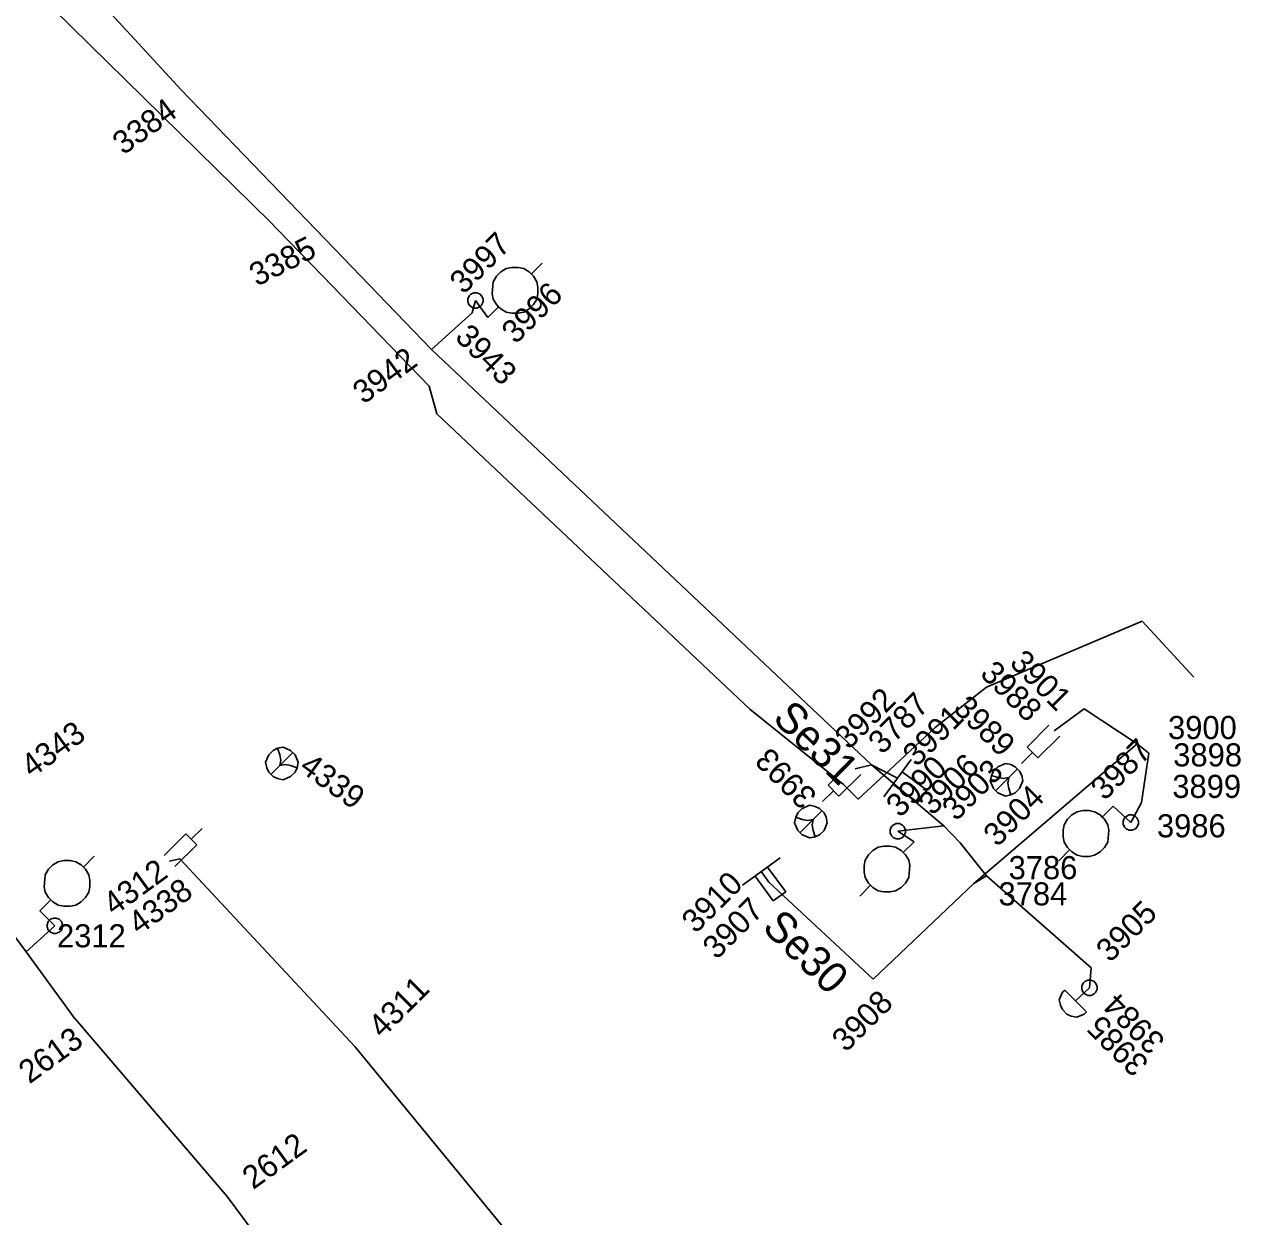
# Model space of a CAD drawing. Extents: x -535557 to -534097, y -1142175 to -1136716.
# Drawn here: x -534981.31 to -534941.83, y -1138903.19 to -1138864.49 of the extents above; entities that cross this region are included whole.
import ezdxf

# ---------------------------------------------------------------- set-up
doc = ezdxf.new("R2010")
doc.units = 0
for name, color, linetype in [('Default', 7, 'Continuous'), ('GIS_vektor_sdelovaci_kabely_CD', 7, 'Continuous'), ('SS_SZDC', 7, 'Continuous')]:
    doc.layers.add(name, color=color, linetype=linetype)

# ---------------------------------------------------------------- blocks, each defined once
blk = doc.blocks.new('POINT_DISPLAY')
at = {"layer": 'Default'}
blk.add_line((0, 0), (0, 0), dxfattribs=at)

msp = doc.modelspace()

# ---------------------------------------------------------------- linework, layer by layer
at = {"layer": 'GIS_vektor_sdelovaci_kabely_CD'}
msp.add_lwpolyline([(-534980.378, -1138863.98), (-534973.325, -1138870.913), (-534973.094, -1138871.151), (-534971.638, -1138872.653), (-534968.166, -1138876.234), (-534967.918, -1138877.131), (-534957.767, -1138886.721), (-534954.728, -1138889.162), (-534954.252, -1138889.638), (-534953.383, -1138888.842), (-534951.746, -1138887.317), (-534950.076, -1138886.002), (-534945.025, -1138883.863), (-534943.35, -1138885.685)], dxfattribs=at)
at = {"layer": 'SS_SZDC'}
for p, q in [((-534986.09, -1138855.87), (-534976.22, -1138866.62)), ((-534976.22, -1138866.62), (-534972.13, -1138870.86)), ((-534972.13, -1138870.86), (-534968.09, -1138875.04)), ((-534965.845, -1138872.525), (-534965.668, -1138872.419)), ((-534965.668, -1138872.419), (-534965.492, -1138872.383)), ((-534965.492, -1138872.383), (-534965.28, -1138872.383)), ((-534965.28, -1138872.383), (-534965.103, -1138872.419)), ((-534965.103, -1138872.419), (-534964.926, -1138872.525)), ((-534964.855, -1138872.595), (-534964.502, -1138872.242)), ((-534966.128, -1138873.232), (-534966.093, -1138872.843)), ((-534966.093, -1138872.843), (-534965.987, -1138872.666)), ((-534965.987, -1138872.666), (-534965.845, -1138872.525)), ((-534964.926, -1138872.525), (-534964.785, -1138872.666)), ((-534964.785, -1138872.666), (-534964.679, -1138872.843)), ((-534964.679, -1138872.843), (-534964.643, -1138873.02)), ((-534966.87, -1138873.3), (-534966.82, -1138873.25)), ((-534966.82, -1138873.25), (-534966.72, -1138873.2)), ((-534966.72, -1138873.2), (-534966.62, -1138873.2)), ((-534966.62, -1138873.2), (-534966.52, -1138873.25)), ((-534966.52, -1138873.25), (-534966.47, -1138873.3)), ((-534966.093, -1138873.408), (-534966.128, -1138873.232)), ((-534964.643, -1138873.232), (-534964.679, -1138873.408)), ((-534964.643, -1138873.02), (-534964.643, -1138873.232)), ((-534966.92, -1138873.4), (-534966.87, -1138873.3)), ((-534966.92, -1138873.5), (-534966.92, -1138873.4)), ((-534966.87, -1138873.6), (-534966.92, -1138873.5)), ((-534966.82, -1138873.65), (-534966.87, -1138873.6)), ((-534966.72, -1138873.7), (-534966.82, -1138873.65)), ((-534966.77, -1138873.85), (-534966.67, -1138873.45)), ((-534966.67, -1138873.45), (-534966.27, -1138874.01)), ((-534966.52, -1138873.65), (-534966.62, -1138873.7)), ((-534966.47, -1138873.6), (-534966.52, -1138873.65)), ((-534966.47, -1138873.3), (-534966.42, -1138873.4)), ((-534966.42, -1138873.5), (-534966.47, -1138873.6)), ((-534966.42, -1138873.4), (-534966.42, -1138873.5)), ((-534966.27, -1138874.01), (-534965.916, -1138873.656)), ((-534965.987, -1138873.585), (-534966.093, -1138873.408)), ((-534965.916, -1138873.656), (-534965.987, -1138873.585)), ((-534965.845, -1138873.727), (-534965.916, -1138873.656)), ((-534964.785, -1138873.585), (-534964.926, -1138873.727)), ((-534964.679, -1138873.408), (-534964.785, -1138873.585)), ((-534968.09, -1138875.04), (-534966.77, -1138873.85)), ((-534966.62, -1138873.7), (-534966.72, -1138873.7)), ((-534965.668, -1138873.833), (-534965.845, -1138873.727)), ((-534965.492, -1138873.868), (-534965.668, -1138873.833)), ((-534965.28, -1138873.868), (-534965.492, -1138873.868)), ((-534965.103, -1138873.833), (-534965.28, -1138873.868)), ((-534964.926, -1138873.727), (-534965.103, -1138873.833)), ((-534968.09, -1138875.04), (-534953.819, -1138888.53)), ((-534946.909, -1138886.709), (-534947.88, -1138887.42)), ((-534945.189, -1138887.84), (-534946.909, -1138886.709)), ((-534948.763, -1138887.95), (-534948.056, -1138887.243)), ((-534950.489, -1138892.379), (-534945.189, -1138887.84)), ((-534947.703, -1138887.596), (-534948.41, -1138888.303)), ((-534945.189, -1138887.84), (-534944.81, -1138888.149)), ((-534973.48, -1138888.444), (-534973.374, -1138888.197)), ((-534973.374, -1138888.197), (-534973.232, -1138888.055)), ((-534972.596, -1138888.126), (-534973.303, -1138888.833)), ((-534973.232, -1138888.055), (-534973.091, -1138887.985)), ((-534973.091, -1138887.985), (-534972.914, -1138887.949)), ((-534973.02, -1138888.197), (-534973.091, -1138887.985)), ((-534972.985, -1138888.373), (-534973.02, -1138888.197)), ((-534972.914, -1138887.949), (-534972.667, -1138888.055)), ((-534972.667, -1138888.055), (-534972.525, -1138888.197)), ((-534972.525, -1138888.197), (-534972.419, -1138888.444)), ((-534948.587, -1138888.127), (-534948.94, -1138888.48)), ((-534948.41, -1138888.303), (-534948.763, -1138887.95)), ((-534944.81, -1138888.149), (-534945.05, -1138889.75)), ((-534973.444, -1138888.621), (-534973.48, -1138888.444)), ((-534973.374, -1138888.762), (-534973.444, -1138888.621)), ((-534973.02, -1138888.55), (-534972.985, -1138888.373)), ((-534973.02, -1138888.55), (-534972.843, -1138888.515)), ((-534972.843, -1138888.515), (-534972.667, -1138888.55)), ((-534972.667, -1138888.55), (-534972.455, -1138888.621)), ((-534972.455, -1138888.621), (-534972.525, -1138888.762)), ((-534972.419, -1138888.444), (-534972.455, -1138888.621)), ((-534955.223, -1138889.19), (-534954.516, -1138888.483)), ((-534953.819, -1138888.53), (-534954.34, -1138888.659)), ((-534953.819, -1138888.53), (-534951.47, -1138890.51)), ((-534953.819, -1138888.53), (-534952.97, -1138888.959)), ((-534952.529, -1138888.353), (-534953.41, -1138889.566)), ((-534949.854, -1138888.727), (-534949.712, -1138888.585)), ((-534949.783, -1138889.363), (-534949.076, -1138888.656)), ((-534949.712, -1138888.585), (-534949.465, -1138888.479)), ((-534949.465, -1138888.479), (-534949.288, -1138888.515)), ((-534949.288, -1138888.515), (-534949.147, -1138888.585)), ((-534949.147, -1138888.585), (-534949.005, -1138888.727)), ((-534973.232, -1138888.904), (-534973.374, -1138888.762)), ((-534973.091, -1138888.974), (-534973.232, -1138888.904)), ((-534972.914, -1138889.01), (-534973.091, -1138888.974)), ((-534972.667, -1138888.904), (-534972.914, -1138889.01)), ((-534972.525, -1138888.762), (-534972.667, -1138888.904)), ((-534954.163, -1138888.836), (-534954.87, -1138889.543)), ((-534952.823, -1138888.757), (-534952.014, -1138889.345)), ((-534949.96, -1138889.045), (-534949.924, -1138888.868)), ((-534949.854, -1138889.292), (-534949.96, -1138889.045)), ((-534949.924, -1138888.868), (-534949.854, -1138888.727)), ((-534949.712, -1138888.939), (-534949.924, -1138888.868)), ((-534949.536, -1138888.974), (-534949.712, -1138888.939)), ((-534949.359, -1138888.939), (-534949.536, -1138888.974)), ((-534949.359, -1138888.939), (-534949.394, -1138889.116)), ((-534949.005, -1138888.727), (-534948.935, -1138888.868)), ((-534948.899, -1138889.045), (-534949.005, -1138889.292)), ((-534948.935, -1138888.868), (-534948.899, -1138889.045)), ((-534955.047, -1138889.367), (-534955.4, -1138889.72)), ((-534954.87, -1138889.543), (-534955.223, -1138889.19)), ((-534952.307, -1138889.75), (-534953.116, -1138889.162)), ((-534952.014, -1138889.345), (-534952.307, -1138889.75)), ((-534949.712, -1138889.434), (-534949.854, -1138889.292)), ((-534949.465, -1138889.54), (-534949.712, -1138889.434)), ((-534949.394, -1138889.116), (-534949.359, -1138889.292)), ((-534949.359, -1138889.292), (-534949.288, -1138889.504)), ((-534949.147, -1138889.434), (-534949.288, -1138889.504)), ((-534949.005, -1138889.292), (-534949.147, -1138889.434)), ((-534956.062, -1138889.945), (-534955.815, -1138889.839)), ((-534955.815, -1138889.839), (-534955.638, -1138889.875)), ((-534949.288, -1138889.504), (-534949.465, -1138889.54)), ((-534945.05, -1138889.75), (-534945.399, -1138890.399)), ((-534956.31, -1138890.405), (-534956.274, -1138890.228)), ((-534956.274, -1138890.228), (-534956.204, -1138890.087)), ((-534956.062, -1138890.299), (-534956.274, -1138890.228)), ((-534956.204, -1138890.087), (-534956.062, -1138889.945)), ((-534956.133, -1138890.723), (-534955.426, -1138890.016)), ((-534955.638, -1138889.875), (-534955.497, -1138889.945)), ((-534955.497, -1138889.945), (-534955.355, -1138890.087)), ((-534955.355, -1138890.087), (-534955.285, -1138890.228)), ((-534955.285, -1138890.228), (-534955.249, -1138890.405)), ((-534947.454, -1138890.294), (-534947.313, -1138890.152)), ((-534947.313, -1138890.152), (-534947.136, -1138890.046)), ((-534947.136, -1138890.046), (-534946.959, -1138890.011)), ((-534946.959, -1138890.011), (-534946.747, -1138890.011)), ((-534946.747, -1138890.011), (-534946.571, -1138890.046)), ((-534946.571, -1138890.046), (-534946.394, -1138890.152)), ((-534946.394, -1138890.152), (-534946.323, -1138890.223)), ((-534945.97, -1138889.87), (-534946.323, -1138890.223)), ((-534946.323, -1138890.223), (-534946.252, -1138890.294)), ((-534945.399, -1138890.399), (-534945.97, -1138889.87)), ((-534945.649, -1138890.349), (-534945.599, -1138890.249)), ((-534945.599, -1138890.249), (-534945.549, -1138890.199)), ((-534945.549, -1138890.199), (-534945.449, -1138890.149)), ((-534945.449, -1138890.149), (-534945.349, -1138890.149)), ((-534945.349, -1138890.149), (-534945.249, -1138890.199)), ((-534945.249, -1138890.199), (-534945.199, -1138890.249)), ((-534945.199, -1138890.249), (-534945.149, -1138890.349)), ((-534975.892, -1138890.942), (-534975.539, -1138890.589)), ((-534956.204, -1138890.652), (-534956.31, -1138890.405)), ((-534956.062, -1138890.794), (-534956.204, -1138890.652)), ((-534955.886, -1138890.334), (-534956.062, -1138890.299)), ((-534955.709, -1138890.299), (-534955.886, -1138890.334)), ((-534955.709, -1138890.299), (-534955.744, -1138890.476)), ((-534955.744, -1138890.476), (-534955.709, -1138890.652)), ((-534955.709, -1138890.652), (-534955.638, -1138890.864)), ((-534955.355, -1138890.652), (-534955.497, -1138890.794)), ((-534955.249, -1138890.405), (-534955.355, -1138890.652)), ((-534953.21, -1138890.63), (-534953.16, -1138890.53)), ((-534953.21, -1138890.73), (-534953.21, -1138890.63)), ((-534953.16, -1138890.53), (-534953.11, -1138890.48)), ((-534953.11, -1138890.48), (-534953.01, -1138890.43)), ((-534953.01, -1138890.43), (-534952.91, -1138890.43)), ((-534951.47, -1138890.51), (-534952.96, -1138890.68)), ((-534952.91, -1138890.43), (-534952.81, -1138890.48)), ((-534952.81, -1138890.48), (-534952.76, -1138890.53)), ((-534952.76, -1138890.53), (-534952.71, -1138890.63)), ((-534952.71, -1138890.63), (-534952.71, -1138890.73)), ((-534951.47, -1138890.51), (-534950.939, -1138891.059)), ((-534947.596, -1138890.647), (-534947.56, -1138890.471)), ((-534947.596, -1138890.859), (-534947.596, -1138890.647)), ((-534947.56, -1138890.471), (-534947.454, -1138890.294)), ((-534946.252, -1138890.294), (-534946.146, -1138890.471)), ((-534946.146, -1138890.471), (-534946.111, -1138890.647)), ((-534946.111, -1138890.647), (-534946.146, -1138891.036)), ((-534945.649, -1138890.449), (-534945.649, -1138890.349)), ((-534945.599, -1138890.549), (-534945.649, -1138890.449)), ((-534945.549, -1138890.599), (-534945.599, -1138890.549)), ((-534945.449, -1138890.649), (-534945.549, -1138890.599)), ((-534945.349, -1138890.649), (-534945.449, -1138890.649)), ((-534945.249, -1138890.599), (-534945.349, -1138890.649)), ((-534945.199, -1138890.549), (-534945.249, -1138890.599)), ((-534945.149, -1138890.449), (-534945.199, -1138890.549)), ((-534945.149, -1138890.349), (-534945.149, -1138890.449)), ((-534976.776, -1138891.473), (-534976.069, -1138890.766)), ((-534976.069, -1138890.766), (-534975.716, -1138891.119)), ((-534955.815, -1138890.9), (-534956.062, -1138890.794)), ((-534955.638, -1138890.864), (-534955.815, -1138890.9)), ((-534955.497, -1138890.794), (-534955.638, -1138890.864)), ((-534953.16, -1138890.83), (-534953.21, -1138890.73)), ((-534953.11, -1138890.88), (-534953.16, -1138890.83)), ((-534953.01, -1138890.93), (-534953.11, -1138890.88)), ((-534952.91, -1138890.93), (-534953.01, -1138890.93)), ((-534952.96, -1138890.68), (-534952.43, -1138891.02)), ((-534952.81, -1138890.88), (-534952.91, -1138890.93)), ((-534952.76, -1138890.83), (-534952.81, -1138890.88)), ((-534952.43, -1138891.02), (-534952.783, -1138891.373)), ((-534952.71, -1138890.73), (-534952.76, -1138890.83)), ((-534947.56, -1138891.036), (-534947.596, -1138890.859)), ((-534947.454, -1138891.213), (-534947.56, -1138891.036)), ((-534946.146, -1138891.036), (-534946.252, -1138891.213)), ((-534983.869, -1138891.069), (-534981.25, -1138894.6)), ((-534975.716, -1138891.119), (-534976.423, -1138891.826)), ((-534954.02, -1138891.621), (-534953.914, -1138891.444)), ((-534953.914, -1138891.444), (-534953.773, -1138891.302)), ((-534953.773, -1138891.302), (-534953.596, -1138891.196)), ((-534953.596, -1138891.196), (-534953.419, -1138891.161)), ((-534953.419, -1138891.161), (-534953.207, -1138891.161)), ((-534953.207, -1138891.161), (-534953.031, -1138891.196)), ((-534953.031, -1138891.196), (-534952.854, -1138891.302)), ((-534952.854, -1138891.302), (-534952.783, -1138891.373)), ((-534952.783, -1138891.373), (-534952.712, -1138891.444)), ((-534952.712, -1138891.444), (-534952.606, -1138891.621)), ((-534950.939, -1138891.059), (-534950.079, -1138892.129)), ((-534947.384, -1138891.284), (-534947.737, -1138891.637)), ((-534947.313, -1138891.354), (-534947.454, -1138891.213)), ((-534947.136, -1138891.46), (-534947.313, -1138891.354)), ((-534946.394, -1138891.354), (-534946.571, -1138891.46)), ((-534946.252, -1138891.213), (-534946.394, -1138891.354)), ((-534980.527, -1138891.916), (-534980.385, -1138891.775)), ((-534980.385, -1138891.775), (-534980.208, -1138891.669)), ((-534980.208, -1138891.669), (-534980.032, -1138891.633)), ((-534980.032, -1138891.633), (-534979.82, -1138891.633)), ((-534979.82, -1138891.633), (-534979.643, -1138891.669)), ((-534979.643, -1138891.669), (-534979.466, -1138891.775)), ((-534979.466, -1138891.775), (-534979.325, -1138891.916)), ((-534979.395, -1138891.845), (-534979.042, -1138891.492)), ((-534976.26, -1138891.579), (-534976.6, -1138891.649)), ((-534970.579, -1138897.67), (-534976.26, -1138891.579)), ((-534956.783, -1138891.549), (-534957.996, -1138892.43)), ((-534954.056, -1138891.797), (-534954.02, -1138891.621)), ((-534954.056, -1138892.009), (-534954.056, -1138891.797)), ((-534952.606, -1138891.621), (-534952.571, -1138891.797)), ((-534952.571, -1138891.797), (-534952.606, -1138892.186)), ((-534946.959, -1138891.496), (-534947.136, -1138891.46)), ((-534946.747, -1138891.496), (-534946.959, -1138891.496)), ((-534946.571, -1138891.46), (-534946.747, -1138891.496)), ((-534980.668, -1138892.482), (-534980.633, -1138892.093)), ((-534980.633, -1138892.093), (-534980.527, -1138891.916)), ((-534979.325, -1138891.916), (-534979.219, -1138892.093)), ((-534979.219, -1138892.093), (-534979.183, -1138892.27)), ((-534957.004, -1138892.945), (-534957.592, -1138892.136)), ((-534957.149, -1138892.329), (-534957.39, -1138891.989)), ((-534957.187, -1138891.843), (-534956.599, -1138892.652)), ((-534954.02, -1138892.186), (-534954.056, -1138892.009)), ((-534953.914, -1138892.363), (-534954.02, -1138892.186)), ((-534952.606, -1138892.186), (-534952.712, -1138892.363)), ((-534950.079, -1138892.129), (-534950.489, -1138892.379)), ((-534950.079, -1138892.129), (-534946.689, -1138895.12)), ((-534980.633, -1138892.658), (-534980.668, -1138892.482)), ((-534979.183, -1138892.482), (-534979.219, -1138892.658)), ((-534979.183, -1138892.27), (-534979.183, -1138892.482)), ((-534953.76, -1138895.479), (-534957.149, -1138892.329)), ((-534953.844, -1138892.434), (-534954.197, -1138892.787)), ((-534953.773, -1138892.504), (-534953.914, -1138892.363)), ((-534953.596, -1138892.61), (-534953.773, -1138892.504)), ((-534950.489, -1138892.379), (-534953.76, -1138895.479)), ((-534953.419, -1138892.646), (-534953.596, -1138892.61)), ((-534953.031, -1138892.61), (-534953.207, -1138892.646)), ((-534952.854, -1138892.504), (-534953.031, -1138892.61)), ((-534952.712, -1138892.363), (-534952.854, -1138892.504)), ((-534980.81, -1138893.26), (-534980.456, -1138892.906)), ((-534980.527, -1138892.835), (-534980.633, -1138892.658)), ((-534980.456, -1138892.906), (-534980.527, -1138892.835)), ((-534980.385, -1138892.977), (-534980.456, -1138892.906)), ((-534980.208, -1138893.083), (-534980.385, -1138892.977)), ((-534979.466, -1138892.977), (-534979.643, -1138893.083)), ((-534979.325, -1138892.835), (-534979.466, -1138892.977)), ((-534979.219, -1138892.658), (-534979.325, -1138892.835)), ((-534956.599, -1138892.652), (-534957.004, -1138892.945)), ((-534953.207, -1138892.646), (-534953.419, -1138892.646)), ((-534980.319, -1138893.75), (-534980.81, -1138893.26)), ((-534980.032, -1138893.118), (-534980.208, -1138893.083)), ((-534979.82, -1138893.118), (-534980.032, -1138893.118)), ((-534979.643, -1138893.083), (-534979.82, -1138893.118)), ((-534981.25, -1138894.6), (-534980.319, -1138893.75)), ((-534980.567, -1138893.714), (-534980.532, -1138893.608)), ((-534980.567, -1138893.785), (-534980.567, -1138893.714)), ((-534980.532, -1138893.891), (-534980.567, -1138893.785)), ((-534980.532, -1138893.608), (-534980.461, -1138893.537)), ((-534980.461, -1138893.537), (-534980.355, -1138893.502)), ((-534980.355, -1138893.502), (-534980.284, -1138893.502)), ((-534980.284, -1138893.502), (-534980.178, -1138893.537)), ((-534980.178, -1138893.537), (-534980.107, -1138893.608)), ((-534980.107, -1138893.608), (-534980.072, -1138893.714)), ((-534980.072, -1138893.785), (-534980.107, -1138893.891)), ((-534980.072, -1138893.714), (-534980.072, -1138893.785)), ((-534980.461, -1138893.962), (-534980.532, -1138893.891)), ((-534980.355, -1138893.997), (-534980.461, -1138893.962)), ((-534980.284, -1138893.997), (-534980.355, -1138893.997)), ((-534980.178, -1138893.962), (-534980.284, -1138893.997)), ((-534980.107, -1138893.891), (-534980.178, -1138893.962)), ((-534979.71, -1138896.7), (-534981.25, -1138894.6)), ((-534946.689, -1138895.12), (-534946.739, -1138895.76)), ((-534946.739, -1138895.76), (-534947.189, -1138896.19)), ((-534946.989, -1138895.71), (-534946.939, -1138895.61)), ((-534946.989, -1138895.81), (-534946.989, -1138895.71)), ((-534946.939, -1138895.61), (-534946.889, -1138895.56)), ((-534946.889, -1138895.56), (-534946.789, -1138895.51)), ((-534946.789, -1138895.51), (-534946.689, -1138895.51)), ((-534946.689, -1138895.51), (-534946.589, -1138895.56)), ((-534946.589, -1138895.56), (-534946.539, -1138895.61)), ((-534946.539, -1138895.61), (-534946.489, -1138895.71)), ((-534946.489, -1138895.71), (-534946.489, -1138895.81)), ((-534947.614, -1138895.907), (-534947.72, -1138896.154)), ((-534947.72, -1138896.154), (-534947.684, -1138896.331)), ((-534947.543, -1138895.836), (-534947.614, -1138895.907)), ((-534946.836, -1138896.543), (-534947.543, -1138895.836)), ((-534946.939, -1138895.91), (-534946.989, -1138895.81)), ((-534946.889, -1138895.96), (-534946.939, -1138895.91)), ((-534946.789, -1138896.01), (-534946.889, -1138895.96)), ((-534946.689, -1138896.01), (-534946.789, -1138896.01)), ((-534946.589, -1138895.96), (-534946.689, -1138896.01)), ((-534946.539, -1138895.91), (-534946.589, -1138895.96)), ((-534946.489, -1138895.81), (-534946.539, -1138895.91)), ((-534947.684, -1138896.331), (-534947.614, -1138896.472)), ((-534947.614, -1138896.472), (-534947.472, -1138896.614)), ((-534946.907, -1138896.614), (-534946.836, -1138896.543)), ((-534979.71, -1138896.7), (-534974.729, -1138902.54)), ((-534947.472, -1138896.614), (-534947.331, -1138896.684)), ((-534947.331, -1138896.684), (-534947.154, -1138896.72)), ((-534947.154, -1138896.72), (-534946.907, -1138896.614)), ((-534961.229, -1138909.059), (-534970.579, -1138897.67)), ((-534974.729, -1138902.54), (-534970.159, -1138908.639))]:
    msp.add_line(p, q, dxfattribs=at)

# ---------------------------------------------------------------- block references
for p in [(-534976.22, -1138866.62), (-534972.13, -1138870.86), (-534966.67, -1138873.45), (-534966.67, -1138873.45), (-534966.77, -1138873.85), (-534966.27, -1138874.01), (-534968.09, -1138875.04), (-534946.909, -1138886.709), (-534947.88, -1138887.42), (-534945.189, -1138887.84), (-534944.81, -1138888.149), (-534972.949, -1138888.479), (-534954.34, -1138888.659), (-534953.819, -1138888.53), (-534952.97, -1138888.959), (-534949.43, -1138889.01), (-534945.05, -1138889.75), (-534945.97, -1138889.87), (-534955.779, -1138890.37), (-534951.47, -1138890.51), (-534945.399, -1138890.399), (-534945.399, -1138890.399), (-534952.96, -1138890.68), (-534952.96, -1138890.68), (-534952.43, -1138891.02), (-534950.939, -1138891.059), (-534976.6, -1138891.649), (-534976.26, -1138891.579), (-534957.39, -1138891.989), (-534950.079, -1138892.129), (-534957.149, -1138892.329), (-534950.489, -1138892.379), (-534980.81, -1138893.26), (-534980.319, -1138893.75), (-534980.319, -1138893.75), (-534981.25, -1138894.6), (-534946.689, -1138895.12), (-534953.76, -1138895.479), (-534946.739, -1138895.76), (-534946.739, -1138895.76), (-534947.189, -1138896.19), (-534979.71, -1138896.7), (-534970.579, -1138897.67), (-534974.729, -1138902.54)]:
    msp.add_blockref('POINT_DISPLAY', p, dxfattribs=at)

# ---------------------------------------------------------------- texts
for s, height, rotation, p in [('3384', 0.75, 36, (-534978.095, -1138868.751)), ('3997', 0.75, 45, (-534967.048, -1138873.28)), ('3385', 0.75, 27, (-534973.76, -1138873.011)), ('3996', 0.75, 45, (-534965.362, -1138874.895)), ('3943', 0.75, 315, (-534967.37, -1138874.677)), ('3942', 0.75, 36, (-534970.299, -1138876.842)), ('3901', 0.75, 315, (-534949.365, -1138885.25)), ('3988', 0.75, 315, (-534950.324, -1138885.603)), ('3992', 0.75, 45, (-534954.549, -1138888.063)), ('3787', 0.75, 45, (-534953.466, -1138888.218)), ('3989', 0.75, 315, (-534951.194, -1138886.731)), ('Se31', 1, 315.3757, (-534957.062, -1138887.059)), ('3991', 0.75, 45, (-534952.345, -1138888.618)), ('4343', 0.75, 36, (-534981.068, -1138888.97)), ('3987', 0.75, 45, (-534946.245, -1138889.717)), ('4339', 0.75, 324, (-534972.426, -1138888.695)), ('3993', 0.75, 135, (-534955.542, -1138889.494)), ('3990', 0.75, 45, (-534952.886, -1138890.268)), ('3906', 0.75, 45, (-534951.837, -1138890.2)), ('3903', 0.75, 45, (-534951.065, -1138890.382)), ('3904', 0.75, 45, (-534949.727, -1138891.219)), ('4312', 0.75, 36, (-534978.402, -1138893.447)), ('3910', 0.75, 45, (-534959.518, -1138894.027)), ('4338', 0.75, 36, (-534977.587, -1138894.071)), ('3907', 0.75, 45, (-534958.839, -1138894.875)), ('3905', 0.75, 45, (-534946.069, -1138894.972)), ('Se30', 1, 315.3757, (-534957.4, -1138893.845)), ('4311', 0.75, 45, (-534969.69, -1138897.428)), ('3908', 0.75, 45, (-534954.643, -1138897.882)), ('3984', 0.75, 135, (-534944.24, -1138897.454)), ('3985', 0.75, 135, (-534944.77, -1138898.174)), ('2613', 0.75, 36, (-534981.144, -1138898.9)), ('2612', 0.75, 36, (-534973.883, -1138902.334))]:
    msp.add_text(s, height=height, rotation=rotation, dxfattribs=at).set_placement(p)
for s, p in [('3900', (-534944.189, -1138887.69)), ('3898', (-534944.019, -1138888.577)), ('3899', (-534944.05, -1138889.599)), ('3986', (-534944.549, -1138890.879)), ('3786', (-534949.363, -1138892.238)), ('3784', (-534949.69, -1138893.088)), ('2312', (-534980.25, -1138894.45))]:
    msp.add_text(s, height=0.75, dxfattribs=at).set_placement(p)

doc.saveas('drawing.dxf')
